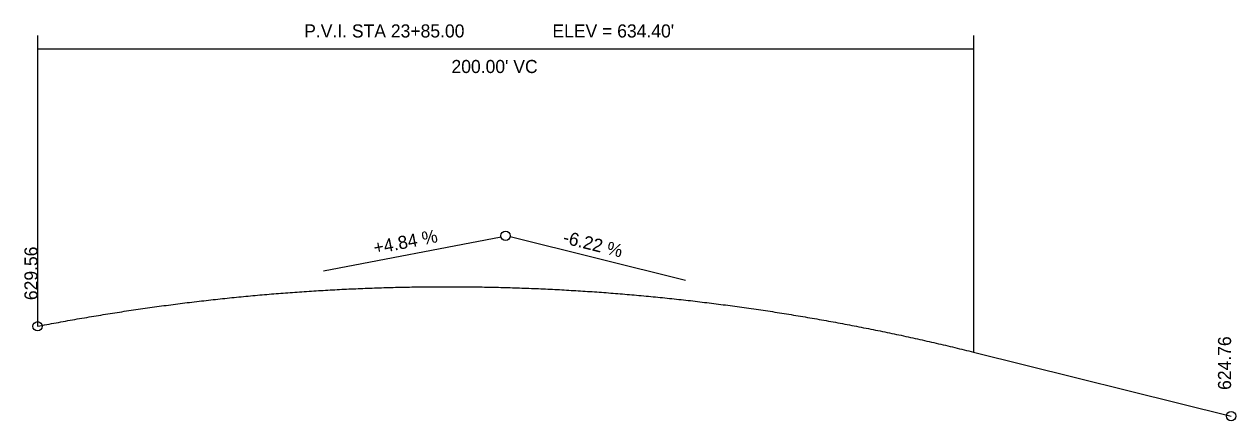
# Model space of a CAD drawing. Extents: x 1869622 to 1870464, y 422115 to 423925.
# Drawn here: x 1869959.1 to 1870217.9, y 422392.6 to 422477.4 of the extents above; entities that cross this region are included whole.
import ezdxf

# ---------------------------------------------------------------- set-up
doc = ezdxf.new("R2010")
doc.units = 0
doc.layers.add('PF_P_Grade_Line', color=7, linetype='Continuous')
doc.layers.add('PF_P_Text', color=7, linetype='Continuous')

msp = doc.modelspace()

# ---------------------------------------------------------------- linework, layer by layer
at = {"layer": 'PF_P_Grade_Line'}
msp.add_line((1870161.94, 422407.3), (1870216.94, 422393.62), dxfattribs=at)
msp.add_spline([(1869961.94, 422412.82), (1869965.94, 422413.58), (1869969.94, 422414.3), (1869973.94, 422414.99), (1869977.94, 422415.64), (1869981.94, 422416.25), (1869985.94, 422416.83), (1869989.94, 422417.37), (1869993.94, 422417.88), (1869997.94, 422418.36), (1870001.94, 422418.8), (1870005.94, 422419.2), (1870009.94, 422419.57), (1870013.94, 422419.9), (1870017.94, 422420.19), (1870021.94, 422420.45), (1870025.94, 422420.68), (1870029.94, 422420.87), (1870033.94, 422421.03), (1870037.94, 422421.15), (1870041.94, 422421.23), (1870045.94, 422421.28), (1870049.94, 422421.29), (1870053.94, 422421.27), (1870057.94, 422421.21), (1870061.94, 422421.12), (1870065.94, 422420.99), (1870069.94, 422420.83), (1870073.94, 422420.63), (1870077.94, 422420.39), (1870081.94, 422420.13), (1870085.94, 422419.82), (1870089.94, 422419.48), (1870093.94, 422419.1), (1870097.94, 422418.69), (1870101.94, 422418.25), (1870105.94, 422417.76), (1870109.94, 422417.25), (1870113.94, 422416.69), (1870117.94, 422416.11), (1870121.94, 422415.48), (1870125.94, 422414.82), (1870129.94, 422414.13), (1870133.94, 422413.4), (1870137.94, 422412.63), (1870141.94, 422411.83), (1870145.94, 422411), (1870149.94, 422410.13), (1870153.94, 422409.22), (1870157.94, 422408.28), (1870161.94, 422407.3)], degree=3, dxfattribs=at)
at = {"layer": 'PF_P_Text'}
for p, q in [((1869961.94, 422474.98), (1869961.94, 422412.82)), ((1870161.94, 422474.98), (1870161.94, 422407.3)), ((1869961.94, 422472.18), (1870161.94, 422472.18)), ((1870023.06, 422424.65), (1870060.96, 422431.99)), ((1870100.37, 422422.62), (1870062.91, 422431.94))]:
    msp.add_line(p, q, dxfattribs=at)
for centre in [(1870061.94, 422432.18), (1869961.94, 422412.82), (1870216.94, 422393.62)]:
    msp.add_circle(centre, 1, dxfattribs=at)

# ---------------------------------------------------------------- texts
for s, p in [('P.V.I. STA 23+85.00', (1870018.91, 422474.58)), ("ELEV = 634.40'", (1870071.94, 422474.58)), ("200.00' VC", (1870050.38, 422466.98))]:
    msp.add_text(s, height=2.8, dxfattribs=at).set_placement(p)
for s, rotation, p in [('+4.84 %', 10.9543, (1870034.01, 422428.2)), ('-6.22 %', 346.0306, (1870074.02, 422430.62)), ('629.56', 90, (1869961.94, 422418.42)), ('624.76', 90, (1870216.94, 422399.22))]:
    msp.add_text(s, height=2.8, rotation=rotation, dxfattribs=at).set_placement(p)

doc.saveas('drawing.dxf')
